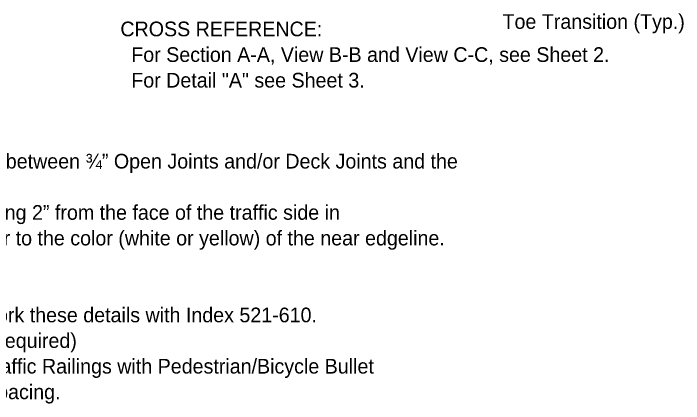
# Model space of a CAD drawing. Extents: x 0 to 40.8, y 1 to 28.
# Drawn here: x 29.77 to 38.96, y 3.47 to 8.83 of the extents above; entities that cross this region are included whole.
import ezdxf

# ---------------------------------------------------------------- set-up
doc = ezdxf.new("R2010")
doc.units = 0
doc.layers.add('Dimension', color=7, linetype='Continuous')
doc.layers.add('TextStructures', color=7, linetype='Continuous')

msp = doc.modelspace()

# ---------------------------------------------------------------- texts
at = {"layer": 'Dimension'}
for s, p in [('CROSS REFERENCE:', (31.2355, 8.5122)), ('  For Section A-A, View B-B and View C-C, see Sheet 2.', (31.2355, 8.1602)), ('  For Detail "A" see Sheet 3.', (31.2355, 7.8082))]:
    msp.add_text(s, height=0.2016, dxfattribs=at).set_placement(p)
at = {"layer": 'TextStructures'}
for s, height, p in [('Toe Transition (Typ.)', 0.2016, (36.4798, 8.6143)), ('7. V-Grooves: Construct ½” V-Grooves plumb. Space V-Grooves equally between ¾” Open Joints and/or Deck Joints and the', 0.2016004, (20.9279, 6.6962)), ('8. Barrier Delineators: Install Barrier Delineators on top of the Traffic Railing 2” from the face of the traffic side in', 0.2016004, (20.9279, 5.9922)), ('   accordance with Specification Section 705. Match the Barrier Delineator to the color (white or yellow) of the near edgeline.', 0.2016004, (20.9279, 5.6402)), ('  B.  Transition to 38” Concrete Barriers: see Detail “B” and View C-C. Work these details with Index 521-610.', 0.2016004, (20.9279, 4.5842)), ('10. See Superstructure Plans for drainage slot locations and size (when required)', 0.2016, (20.9279, 4.2322)), ('11. For embedded conduit and junction boxes see Index 630-010. For Traffic Railings with Pedestrian/Bicycle Bullet', 0.2016004, (20.9279, 3.8802)), ('    Railings see Index 515-021 and 515-022 for Notes, Details and post spacing.', 0.2016, (20.9279, 3.5282))]:
    msp.add_text(s, height=height, dxfattribs=at).set_placement(p)

doc.saveas('drawing.dxf')
